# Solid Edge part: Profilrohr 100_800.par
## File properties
Username: ahadarics
Dokumentum tartalom típus: 0
Author: ahadarics
Last saved by: ahadarics
Revision: 97
Sűrűség: 0,000 kg/m^3
Pontosság: 0,990
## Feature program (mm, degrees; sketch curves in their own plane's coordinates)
base feature "unnamed BaseFeature 1"
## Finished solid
Body 1: solid body, 179 faces, 531 edges, 354 vertices.
  Faces by surface: cylinder 109, plane 70
  Edges by curve: line 313, circle 218
Bounding box of the edges (mm): 105.500 x 105.500 x 857.000, from (-52.75, -52.75, -816) to (52.75, 52.75, 41).
Cylindrical faces by radius (mm): R0.1 x16, R0.2 x30, R0.5 x28, R1 x10, R4.6 x8, R5.7 x4, R7.5 x4, R50 x1, R52.7 x8
Planar faces by outward normal: +x 6, +y 6, +z 1, -x 4, -y 4, -z 1, oblique 48
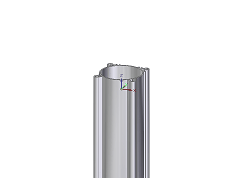
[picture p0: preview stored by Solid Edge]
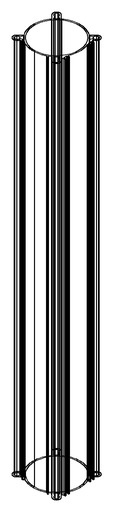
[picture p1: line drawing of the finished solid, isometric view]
